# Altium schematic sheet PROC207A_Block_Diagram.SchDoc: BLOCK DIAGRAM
size 431 x 279 mm; Date: Not shown in title block; ApprovedBy: Not shown in title block; CheckedBy: Not shown in title block; Author: Not shown in title block; CompanyName: Not shown in title block; DrawnBy: Mistral; Organization: Not shown in title block; Address1: Not shown in title block; Address2: Not shown in title block; Address3: Not shown in title block; Address4: Not shown in title block; DocumentNumber: 1; Revision: Use project parameter SCH_Rev; SheetNumber: 1; SheetTotal: 18; PageSetup: Record=PageOptions¦CenterHorizontal=True¦CenterVertical=True¦PrintScale=1.00¦XCorrection=1.00¦YCorrection=1.00¦PrintKind=0¦BorderSize=5000000¦LeftOffset=0¦BottomOffset=0¦Orientation=2¦PaperLength=1000¦PaperWidth=1000¦Scale=100¦PaperSource=15¦PrintQuality=600¦MediaType=1¦DitherType=10¦PaperKind=Letter¦PrintScaleMode=1
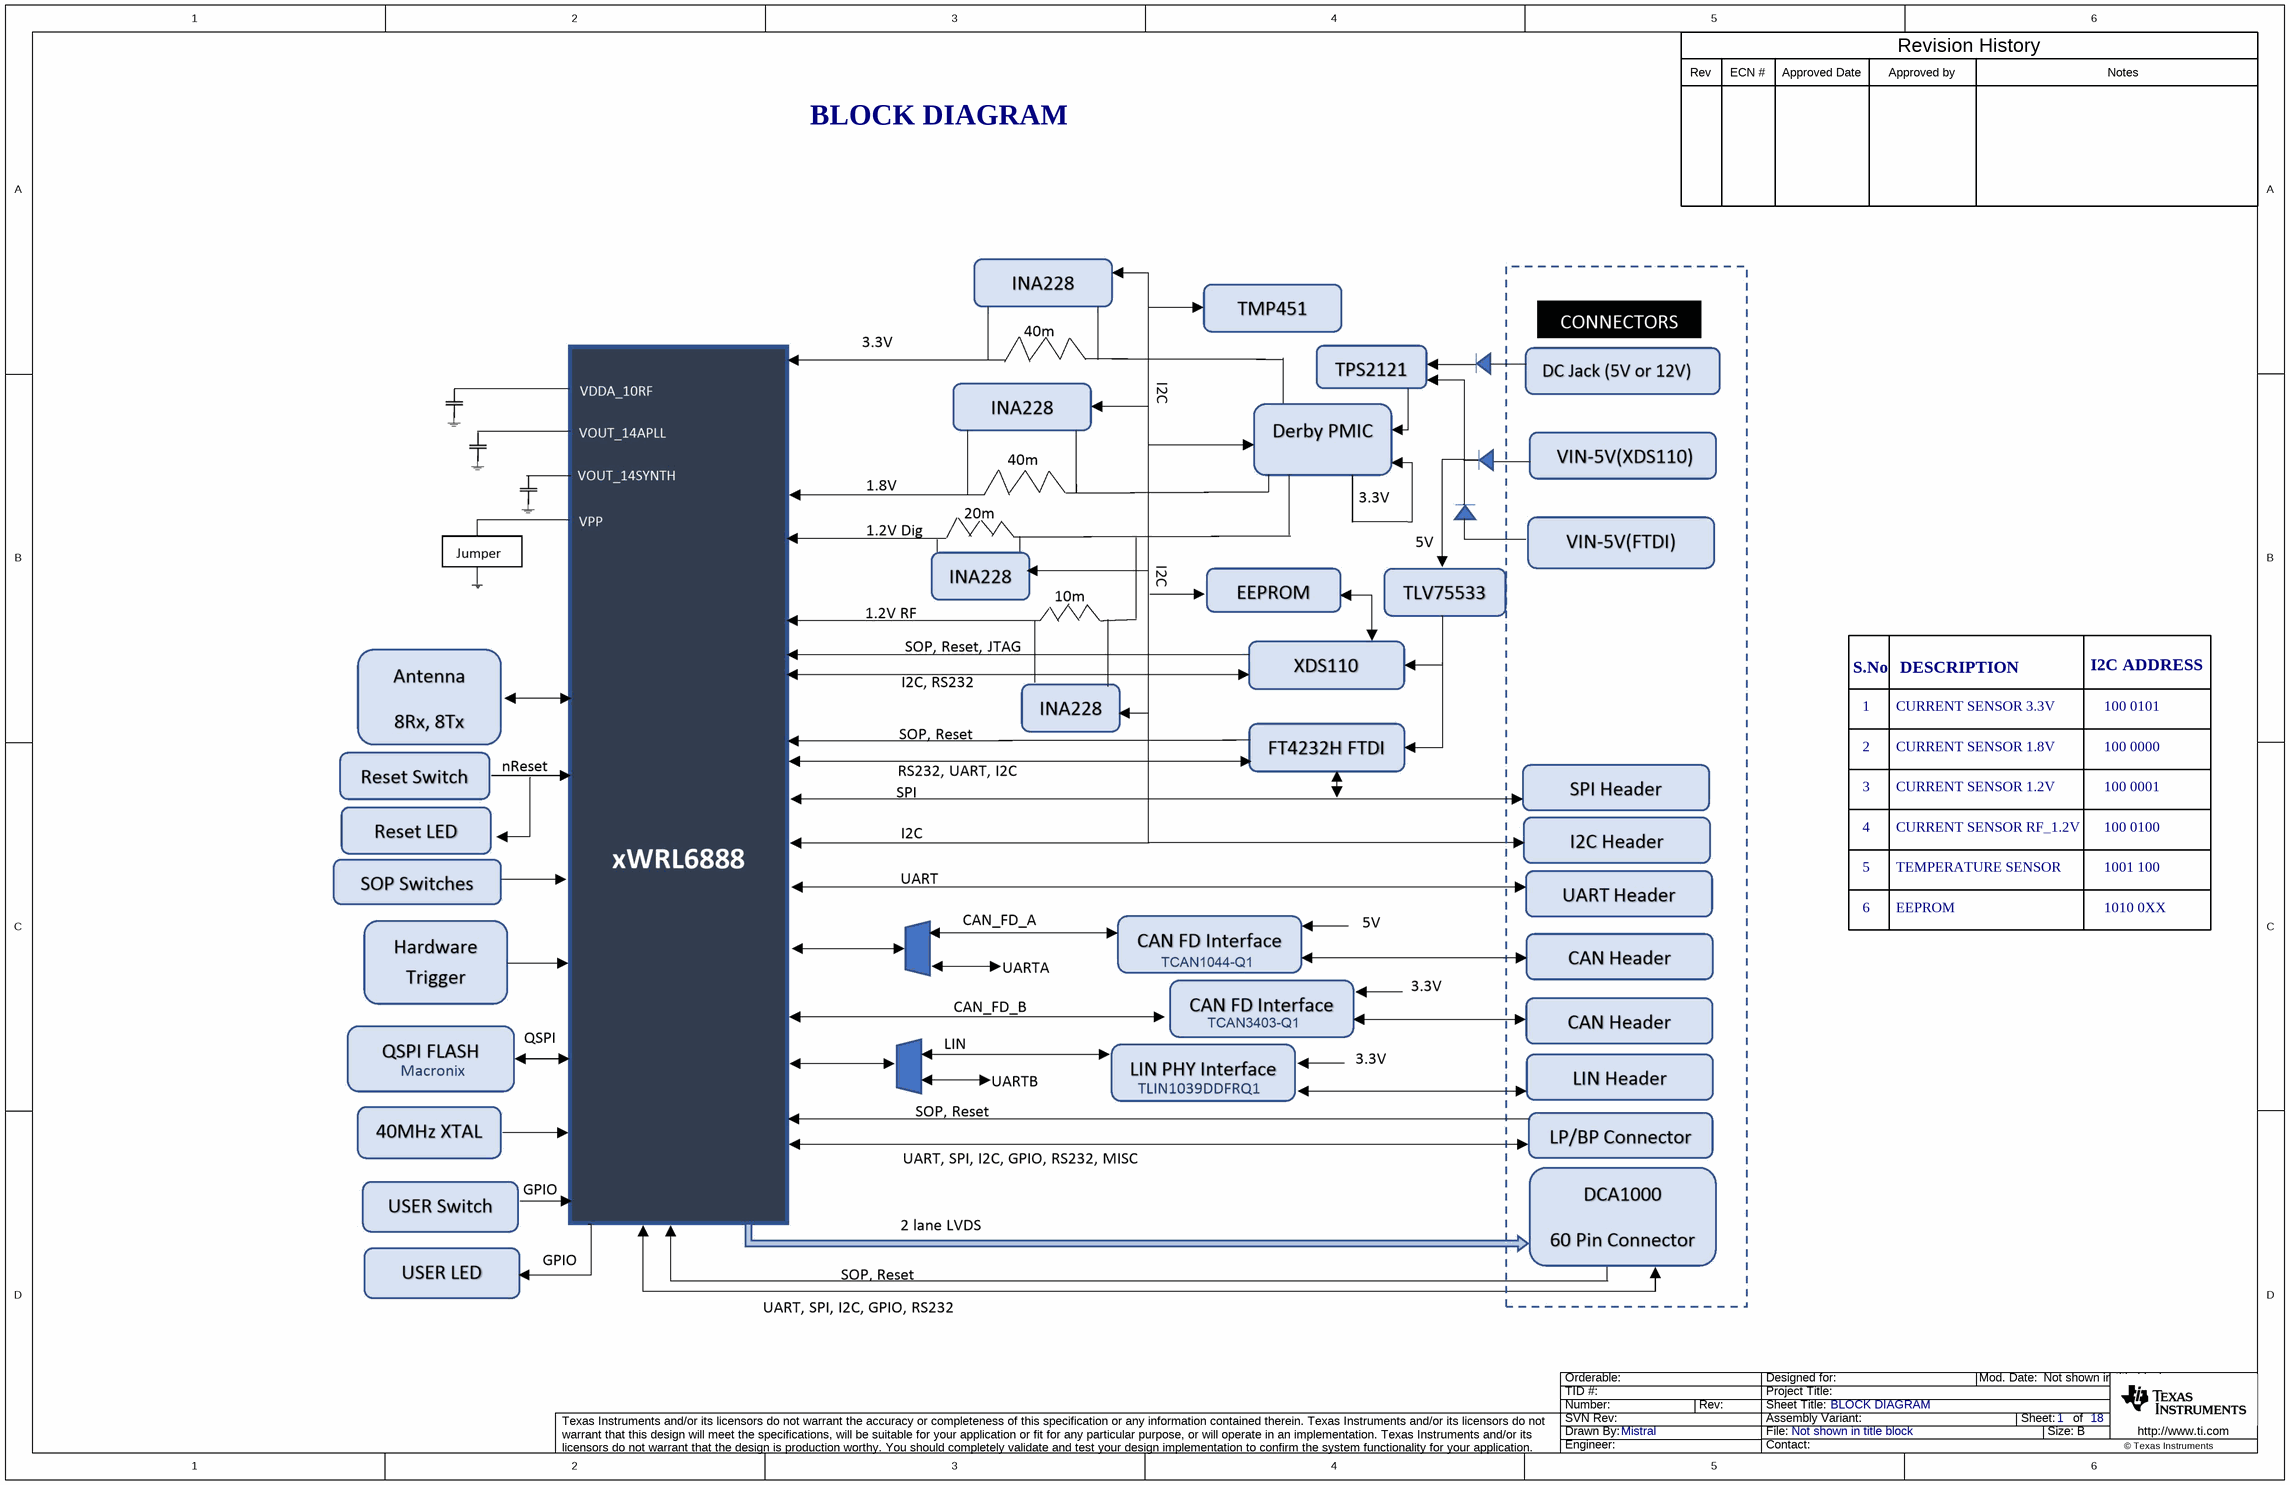
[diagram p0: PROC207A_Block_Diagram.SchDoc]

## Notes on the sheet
- Rev
- ECN #
- Approved Date
- Approved by
- Revision History
- Notes
- BLOCK DIAGRAM
- S.No
- DESCRIPTION
- I2C ADDRESS
- 1
- 2
- CURRENT SENSOR 3.3V
- CURRENT SENSOR 1.8V
- 100 0000
- 100 0101
- 3
- 4
- CURRENT SENSOR 1.2V
- CURRENT SENSOR RF_1.2V
- 100 0001
- 100 0100
- 5
- TEMPERATURE SENSOR
- 1001 100
- 6
- EEPROM
- 1010 0XX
